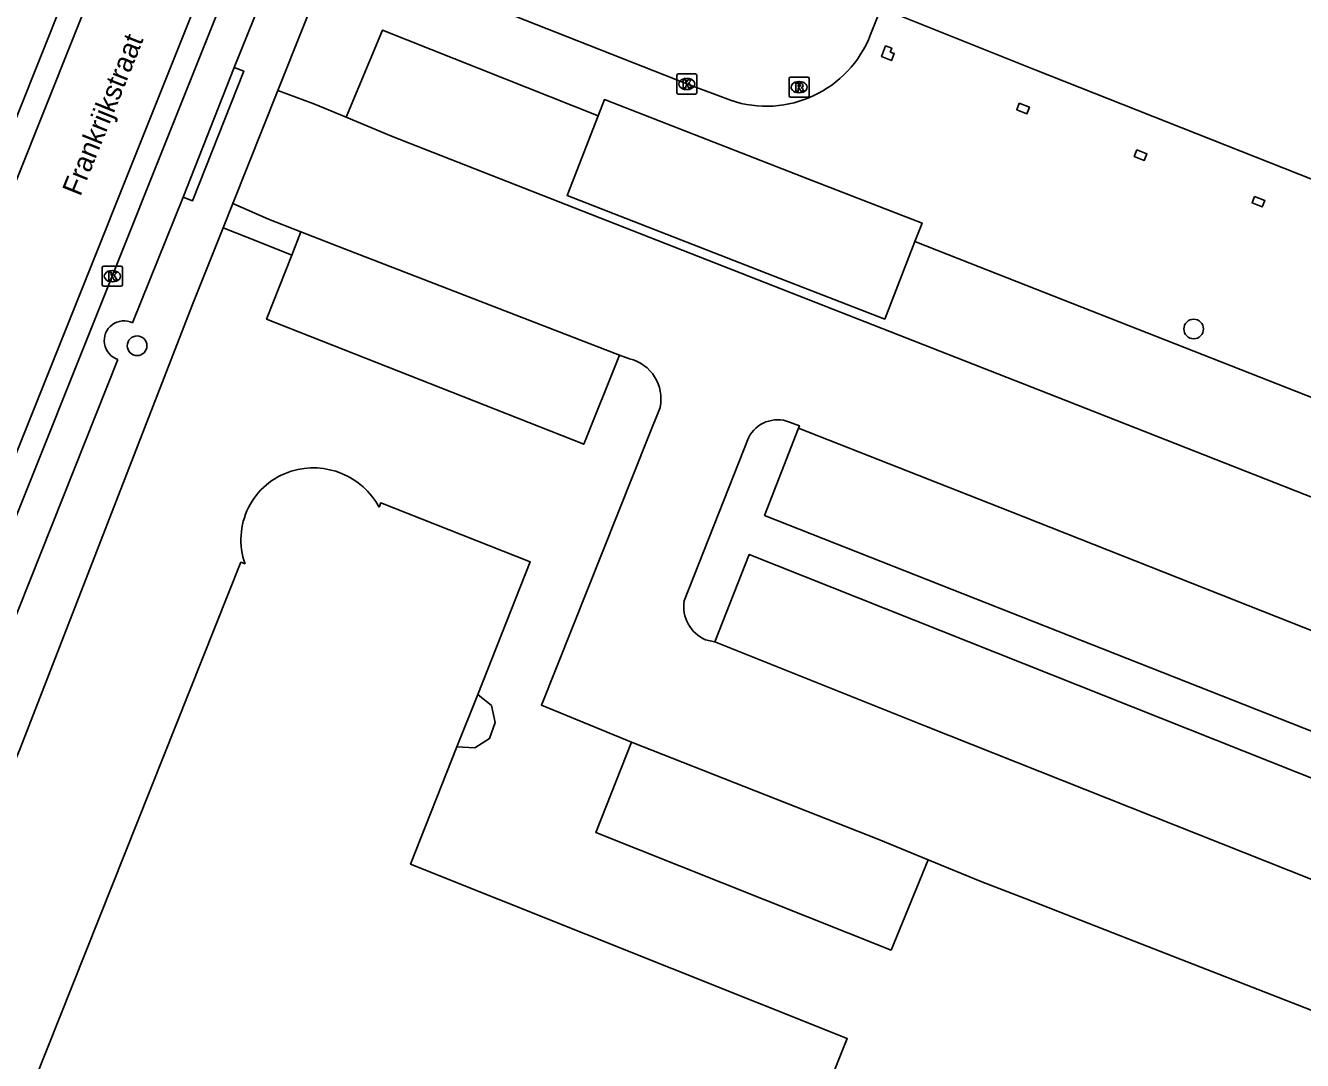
# Model space of a CAD drawing. Extents: x 160026 to 161302, y 384757 to 385701.
# Drawn here: x 160395 to 160458.6, y 384880.6 to 384932.1 of the extents above; entities that cross this region are included whole.
import ezdxf

# ---------------------------------------------------------------- set-up
doc = ezdxf.new("R2010")
doc.units = 0
for name, color, linetype in [('IMGEO_Boom', 7, 'Continuous'), ('IMGEO_Kolk', 7, 'Continuous'), ('IMGEO_Openbare_ruimte_label', 7, 'Continuous'), ('IMGEO_Pand', 7, 'Continuous'), ('IMGEO_Pand_overbouw', 7, 'Continuous'), ('IMGEO_Parkeervlak_open', 7, 'Continuous'), ('IMGEO_Rijbaan_lokaal_open', 7, 'Continuous'), ('IMGEO_Rioolput', 7, 'Continuous'), ('IMGEO_Voetpad_open', 7, 'Continuous')]:
    doc.layers.add(name, color=color, linetype=linetype)

msp = doc.modelspace()

# ---------------------------------------------------------------- linework, layer by layer
at = {"layer": 'IMGEO_Boom'}
for centre in [(160453.188, 384916.973), (160400.596, 384916.136)]:
    msp.add_circle(centre, 0.489, dxfattribs=at)
at = {"layer": 'IMGEO_Kolk'}
for p, q in [((160427.458, 384928.745), (160427.458, 384929.597)), ((160427.533, 384929.671), (160428.385, 384929.671)), ((160427.946, 384929.451), (160427.971, 384929.451)), ((160428.459, 384929.597), (160428.459, 384928.745)), ((160428.385, 384928.671), (160427.533, 384928.671)), ((160427.969, 384928.891), (160427.944, 384928.891)), ((160398.864, 384919.175), (160398.864, 384920.027)), ((160398.939, 384920.101), (160399.791, 384920.101)), ((160399.352, 384919.881), (160399.377, 384919.881)), ((160399.865, 384920.027), (160399.865, 384919.175)), ((160399.791, 384919.101), (160398.939, 384919.101)), ((160399.375, 384919.321), (160399.35, 384919.321))]:
    msp.add_line(p, q, dxfattribs=at)
for points in [[(160427.458, 384928.745), (160427.458, 384929.597)], [(160427.533, 384929.671), (160428.385, 384929.671)], [(160427.779, 384929.371), (160427.902, 384929.371), (160427.902, 384929.22), (160428.032, 384929.371), (160428.196, 384929.371), (160428.05, 384929.22), (160428.203, 384928.971), (160428.051, 384928.971), (160427.966, 384929.135), (160427.902, 384929.068), (160427.902, 384928.971), (160427.779, 384928.971), (160427.779, 384929.371)], [(160428.459, 384929.597), (160428.459, 384928.745)], [(160428.385, 384928.671), (160427.533, 384928.671)], [(160398.864, 384919.175), (160398.864, 384920.027)], [(160398.939, 384920.101), (160399.791, 384920.101)], [(160399.185, 384919.801), (160399.308, 384919.801), (160399.308, 384919.65), (160399.438, 384919.801), (160399.602, 384919.801), (160399.456, 384919.65), (160399.609, 384919.401), (160399.457, 384919.401), (160399.372, 384919.565), (160399.308, 384919.498), (160399.308, 384919.401), (160399.185, 384919.401), (160399.185, 384919.801)], [(160399.865, 384920.027), (160399.865, 384919.175)], [(160399.791, 384919.101), (160398.939, 384919.101)]]:
    msp.add_lwpolyline(points, dxfattribs=at)
for centre, start, end in [((160427.535, 384929.595), 91.55205, 178.44795), ((160427.535, 384929.595), 91.55205, 178.44795), ((160428.383, 384929.595), 1.55205, 88.44795), ((160428.383, 384929.595), 1.55205, 88.44795), ((160427.535, 384928.747), 181.55205, 268.44795), ((160427.535, 384928.747), 181.55205, 268.44795), ((160428.383, 384928.747), 271.55205, 358.44795), ((160428.383, 384928.747), 271.55205, 358.44795), ((160398.941, 384920.025), 91.55205, 178.44795), ((160398.941, 384920.025), 91.55205, 178.44795), ((160399.789, 384920.025), 1.55205, 88.44795), ((160399.789, 384920.025), 1.55205, 88.44795), ((160398.941, 384919.177), 181.55205, 268.44795), ((160398.941, 384919.177), 181.55205, 268.44795), ((160399.789, 384919.177), 271.55205, 358.44795), ((160399.789, 384919.177), 271.55205, 358.44795)]:
    msp.add_arc(centre, 0.0765, start, end, dxfattribs=at)
for centre, major_axis, ratio, start_param, end_param in [((160427.945, 384929.171), (-0.387, 0.002), 0.722429, 4.712389, 7.853982), ((160427.97, 384929.171), (-0.39, 0.002), 0.717154, 1.570796, 4.712389), ((160399.351, 384919.601), (-0.387, 0.002), 0.722429, 4.712389, 7.853982), ((160399.376, 384919.601), (-0.39, 0.002), 0.717154, 1.570796, 4.712389)]:
    msp.add_ellipse(centre, major_axis=major_axis, ratio=ratio, start_param=start_param, end_param=end_param, dxfattribs=at)
at = {"layer": 'IMGEO_Pand'}
for points in [[(160443.479, 384945.268), (160443.259, 384944.769), (160443.496, 384944.664), (160441.808, 384940.436), (160441.587, 384940.531), (160441.387, 384940.037), (160441.612, 384939.946), (160439.923, 384935.718), (160439.714, 384935.798), (160439.509, 384935.269), (160439.713, 384935.189), (160438.653, 384932.538), (160445.305, 384929.876), (160478.862, 384916.6)], [(160438.085, 384930.759), (160438.162, 384930.953), (160437.85, 384931.068), (160437.649, 384930.535), (160438.138, 384930.34), (160438.28, 384930.684), (160438.085, 384930.759)], [(160423.538, 384927.577), (160423.855, 384928.392), (160434.063, 384924.423), (160439.671, 384922.243), (160439.312, 384921.321)], [(160444.508, 384928.216), (160444.381, 384927.891), (160444.884, 384927.692), (160445.012, 384928.018), (160444.508, 384928.216)], [(160423.538, 384927.577), (160421.997, 384923.615), (160432.261, 384919.624), (160437.813, 384917.466), (160439.312, 384921.321)], [(160450.354, 384925.887), (160450.227, 384925.561), (160450.73, 384925.363), (160450.858, 384925.688), (160450.354, 384925.887)], [(160456.222, 384923.574), (160456.096, 384923.248), (160456.598, 384923.05), (160456.726, 384923.376), (160456.222, 384923.574)], [(160412.642, 384908.106), (160412.733, 384908.325), (160420.167, 384905.387), (160417.549, 384898.775), (160416.515, 384896.163), (160414.208, 384890.335), (160435.946, 384881.652), (160429.921, 384866.554), (160428.854, 384863.881), (160427.65, 384860.863), (160427.449, 384860.941)], [(160404.751, 384873.083), (160405.674, 384875.447), (160395.472, 384879.515), (160405.765, 384905.361), (160405.969, 384905.287)]]:
    msp.add_lwpolyline(points, dxfattribs=at)
for centre, radius, start, end in [((160409.333, 384906.484), 3.571, 107.28553, 199.59432), ((160409.366, 384906.333), 3.725, 28.41931, 107.07652)]:
    msp.add_arc(centre, radius, start, end, dxfattribs=at)
at = {"layer": 'IMGEO_Pand_overbouw'}
msp.add_lwpolyline([(160418.42, 384897.378), (160418.236, 384898.221), (160417.549, 384898.775), (160416.515, 384896.163), (160417.404, 384896.115), (160418.131, 384896.579)], close=True, dxfattribs=at)
at = {"layer": 'IMGEO_Parkeervlak_open'}
for points in [[(160411, 384927.518), (160412.807, 384931.842), (160423.538, 384927.577)], [(160439.312, 384921.321), (160442.044, 384920.242), (160468.993, 384909.67), (160467.26, 384905.381)], [(160424.604, 384915.668), (160422.825, 384911.235), (160407.038, 384917.467), (160408.295, 384920.652)], [(160465.014, 384899.614), (160463.307, 384895.28), (160431.832, 384907.692), (160433.521, 384912.04)], [(160429.352, 384901.402), (160431.065, 384905.752), (160462.478, 384893.25), (160460.719, 384888.916)], [(160439.971, 384890.546), (160438.129, 384886.048), (160423.435, 384891.899), (160425.205, 384896.398)]]:
    msp.add_lwpolyline(points, dxfattribs=at)
at = {"layer": 'IMGEO_Rijbaan_lokaal_open'}
for points in [[(160387.693, 384910.244), (160423.495, 385000), (160443.146, 385049.264)], [(160385.418, 384898), (160385.618, 384898.566), (160388.819, 384909.958), (160424.752, 385000), (160444.248, 385048.841)], [(160448.949, 385047.038), (160436.681, 385016.096), (160430.241, 385000), (160388.913, 384896.667)], [(160382.619, 384876.93), (160386.339, 384887.1), (160431.47, 385000), (160434.346, 385007.194)], [(160437.102, 384931.63), (160440.178, 384939.33), (160442.437, 384945.142)], [(160410.538, 384936.086), (160414.526, 384934.496), (160427.959, 384929.171), (160430.132, 384928.359)], [(160405.361, 384923.214), (160407.607, 384928.852)], [(160411, 384927.518), (160409.395, 384928.189), (160407.607, 384928.852)], [(160467.26, 384905.381), (160465.64, 384906.014), (160446.36, 384913.598), (160413.25, 384926.578), (160411, 384927.518)], [(160408.748, 384921.809), (160407.138, 384922.439), (160405.361, 384923.214)], [(160424.604, 384915.668), (160410.911, 384920.963), (160408.748, 384921.809)], [(160425.099, 384915.491), (160424.604, 384915.668)], [(160425.205, 384896.398), (160420.717, 384898.252), (160426.046, 384911.627), (160426.626, 384913.07)], [(160433.074, 384912.341), (160433.566, 384912.155), (160433.521, 384912.04)], [(160433.521, 384912.04), (160444.014, 384907.909), (160463.579, 384900.162), (160465.014, 384899.614)], [(160427.831, 384903.442), (160431.022, 384911.555)], [(160429.352, 384901.402), (160428.892, 384901.502)], [(160460.719, 384888.916), (160459.073, 384889.572), (160439.893, 384897.187), (160429.352, 384901.402)], [(160439.971, 384890.546), (160437.514, 384891.552), (160425.205, 384896.398)], [(160465.8, 384882.136), (160465.212, 384880.648), (160449.919, 384886.614), (160444.794, 384888.613), (160442.635, 384889.455), (160439.971, 384890.546)]]:
    msp.add_lwpolyline(points, dxfattribs=at)
for centre, radius, start, end in [((160431.913, 384933.624), 5.559, 251.30789, 338.97316), ((160424.618, 384913.496), 2.052, 348.02542, 76.45639), ((160432.48, 384910.821), 1.632, 68.65421, 153.26356), ((160429.591, 384903.145), 1.785, 170.41203, 246.9371)]:
    msp.add_arc(centre, radius, start, end, dxfattribs=at)
at = {"layer": 'IMGEO_Rioolput'}
for p, q in [((160433.047, 384928.586), (160433.047, 384929.438)), ((160433.122, 384929.512), (160433.974, 384929.512)), ((160433.535, 384929.292), (160433.56, 384929.292)), ((160434.048, 384929.438), (160434.048, 384928.586)), ((160433.974, 384928.512), (160433.122, 384928.512)), ((160433.558, 384928.732), (160433.533, 384928.732))]:
    msp.add_line(p, q, dxfattribs=at)
for points in [[(160433.047, 384928.586), (160433.047, 384929.438)], [(160433.122, 384929.512), (160433.974, 384929.512)], [(160433.636, 384929.21), (160433.384, 384929.212), (160433.384, 384928.812)], [(160434.048, 384929.438), (160434.048, 384928.586)], [(160433.974, 384928.512), (160433.122, 384928.512)], [(160433.384, 384928.812), (160433.508, 384928.812), (160433.508, 384928.974), (160433.519, 384928.974)], [(160433.562, 384929.131), (160433.508, 384929.131), (160433.508, 384929.05)], [(160433.508, 384929.05), (160433.56, 384929.05)], [(160433.566, 384928.945), (160433.637, 384928.812), (160433.777, 384928.812), (160433.712, 384928.938)]]:
    msp.add_lwpolyline(points, dxfattribs=at)
for centre, radius, start, end in [((160433.124, 384929.436), 0.0765, 91.55205, 178.44795), ((160433.124, 384929.436), 0.0765, 91.55205, 178.44795), ((160433.635, 384929.1), 0.109, 350.36119, 89.41601), ((160433.972, 384929.436), 0.0765, 1.55205, 88.44795), ((160433.972, 384929.436), 0.0765, 1.55205, 88.44795), ((160433.124, 384928.588), 0.0765, 181.55205, 268.44795), ((160433.124, 384928.588), 0.0765, 181.55205, 268.44795), ((160433.518, 384928.921), 0.0533, 26.02933, 88.69889), ((160433.544, 384929.239), 0.19, 274.7715, 282.96867), ((160433.568, 384929.035), 0.0964, 77.00612, 93.18647), ((160433.582, 384929.092), 0.0378, 276.66336, 79.67722), ((160433.633, 384929.1), 0.112, 277.58423, 350.98172), ((160433.617, 384928.885), 0.108, 29.51342, 73.79051), ((160433.972, 384928.588), 0.0765, 271.55205, 358.44795), ((160433.972, 384928.588), 0.0765, 271.55205, 358.44795)]:
    msp.add_arc(centre, radius, start, end, dxfattribs=at)
for centre, major_axis, ratio, start_param, end_param in [((160433.534, 384929.012), (-0.387, 0.002), 0.722429, 4.712389, 7.853982), ((160433.559, 384929.012), (-0.39, 0.002), 0.717154, 1.570796, 4.712389)]:
    msp.add_ellipse(centre, major_axis=major_axis, ratio=ratio, start_param=start_param, end_param=end_param, dxfattribs=at)
at = {"layer": 'IMGEO_Voetpad_open'}
for points in [[(160407.909, 384936.149), (160407.425, 384934.937), (160405.435, 384929.996)], [(160407.607, 384928.852), (160410.154, 384935.27)], [(160405.435, 384929.996), (160405.9, 384929.813), (160403.354, 384923.361), (160402.889, 384923.544)], [(160405.435, 384929.996), (160402.889, 384923.544)], [(160402.889, 384923.544), (160400.371, 384917.283)], [(160404.882, 384922.015), (160405.361, 384923.214)], [(160404.882, 384922.015), (160403.358, 384918.197), (160394.783, 384896.085), (160382.365, 384866.119)], [(160408.295, 384920.652), (160406.682, 384921.296), (160404.882, 384922.015)], [(160408.295, 384920.652), (160408.748, 384921.809)], [(160399.64, 384915.454), (160389.215, 384889.291), (160385.303, 384879.087)]]:
    msp.add_lwpolyline(points, dxfattribs=at)
msp.add_arc((160399.947, 384916.392), 0.987, 64.57587, 251.85372, dxfattribs=at)

# ---------------------------------------------------------------- texts
at = {"layer": 'IMGEO_Openbare_ruimte_label'}
msp.add_text('Frankrijkstraat', height=1, rotation=68.10285, dxfattribs=at).set_placement((160397.766, 384923.537))

doc.saveas('drawing.dxf')
